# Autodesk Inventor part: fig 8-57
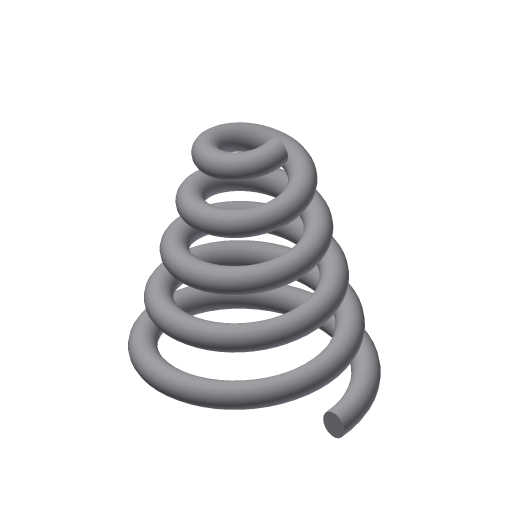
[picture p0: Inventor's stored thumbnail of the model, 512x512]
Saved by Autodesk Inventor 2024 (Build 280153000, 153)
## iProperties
Shininess: 77.0
Length Units: 11269
Angle Units: 11279
Time Units: 11290
Mass Units: 11283
Length Display Precision: 3
Angle Display Precision: 2
Created: 2002-01
Part Number: fig 8-57
Document SubType Name: Modeling
Designer: CADSoft
Density: 1 g/cm^3
Material: Generic
Appearance: Default
Density: 0.0
Volumn: 0.0
Area: 0.0
PropertySet Name: Model Information
Control State: 0
Master: False
Checked Out: False
Author: CADSoft
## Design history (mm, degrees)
sketch "Sketch2"
  geometry: C1 r 2.5 at (-19.895, -0.092)
  constraints: 1 centre point
  dimensions: "d0" = 5 diameter of C1
coil "Coil5" sketch "Sketch2" pitch "d35" = 10; turns "d37" = 5; dims "d36" = 10, "d38" = -15 deg, angle "d39" = 90 deg, angle "d40" = 90 deg, "d41" = 0, "d42" = 0
body "Solid1"
